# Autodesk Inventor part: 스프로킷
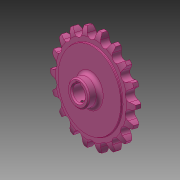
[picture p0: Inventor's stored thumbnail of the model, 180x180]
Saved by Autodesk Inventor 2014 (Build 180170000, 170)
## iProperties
Created: 2016-03
Part Number: 스프로킷
Material: 강철, 탄소
Document SubType Name: Modeling
Designer: mduedu
Density: 7.87 g/cm^3
Mass: 301.818 g
Surface Area: 124.882 cm^2
Volume: 38.3505 cm^3
Appearance: 분홍색
Author: mduedu
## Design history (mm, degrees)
sketch "스케치1"
  geometry: L1 (0, 5)-(29.5, 5); L2 (29.5, 5)-(29.5, 4.1); L3 (30, 3.6)-(33.625, 3.6); L4 (40, 2)-(40, 0); L5 (40, 0)-(0, 0); L6 (0, 0)-(0, 5); L7 (0, -5)-(29.5, -5); L8 (29.5, -5)-(29.5, -4.1); L9 (30, -3.6)-(33.625, -3.6); L10 (40, -2)-(40, 0); L11 (0, 0)-(0, -5); A1 r 13.5 centre (33.625, -9.9) between (40, 2) and (33.625, 3.6); A2 r 13.5 centre (33.625, 9.9) between (33.625, -3.6) and (40, -2); A3 r 0.5 centre (30, 4.1) between (29.5, 4.1) and (30, 3.6); A4 r 0.5 centre (30, -4.1) between (30, -3.6) and (29.5, -4.1); 2 further points
  constraints: 22 end point, 8 point on circle, 6 symmetric about line, 5 tangent, 4 centre point, 4 parallel, 4 point on line, 1 equal radius, 1 horizontal, 1 perpendicular, 1 other
  dimensions: "d0" = 80 diameter of L4 L6; "d2" = 59 diameter of L2 L6; "d3" = 1.6 vertical distance of L4.start L3.end; "d4" = 3.6 distance from line of L4.end L3; "d5" = 5 distance between parallel lines of L5 L1; "d6" = 13.5 radius of A1; "d15" = 0.5 radius of A3
revolve "회전1" sketch "스케치1" stored, may be unused: angle "d7" = 90 deg
sketch "스케치2" dims "d8" = 65.2, "d11" = 80
  geometry: L1 (0, 0)-(0, 32.6); A1 r 36.57 centre (0, 0) between (-16.231, 32.771) and (0, 36.57); A2 r 3.97 centre (0, 36.57) between (-3.866, 35.665) and (0, 32.6); A3 r 12.7 centre (-16.231, 32.771) between (-3.866, 35.665) and (-5.534, 39.615); A4 r 12.7 centre (16.231, 32.771) between (5.534, 39.615) and (3.866, 35.665); A5 r 3.97 centre (0, 36.57) between (0, 32.6) and (3.866, 35.665); A6 r 40 centre (0, 0) between (5.534, 39.615) and (-5.534, 39.615); 2 further points
  constraints: 12 point on circle, 6 centre point, 4 coincident, 3 symmetric about line, 2 end point, 1 point on line, 1 tangent, 1 vertical, 1 vertical alignment, 7 other
  dimensions: "d10" = 73.14 diameter of A1; "d12" = 12.7 radius of A3
extrude "돌출1" cut sketch "스케치2" stored distance "d13" = 10; taper "d14" = 0 deg
sketch "스케치3"
  geometry: C1 r 10 at (0, 0); 1 further point
  constraints: 1 centre point, 1 coincident
  dimensions: "d19" = 20 diameter of C1
extrude "돌출2" join sketch "스케치3" distance "d20" = 9; taper "d21" = 0 deg
fillet "모깎기1" dims "d22" = 3
sketch "스케치4"
  geometry: L1 (-2, 0)-(2, 0); L2 (2, 0)-(2, 7.8); L3 (2, 7.8)-(-2, 7.8); L4 (-2, 7.8)-(-2, 0); C1 r 6 at (0, 0); 2 further points
  constraints: 8 end point, 2 coincident, 2 parallel, 1 centre point, 1 horizontal, 1 midpoint, 1 perpendicular
  dimensions: "d23" = 12 diameter of C1; "d25" = 4 distance of L2.end L3.end; "d26" = 7.8 distance of L1.end L2.end
extrude "돌출3" cut sketch "스케치4" stored distance "d27" = 8; taper "d28" = 0 deg
chamfer "모따기2" distance "d42" = 1; stored, may be unused: second distance "d43" = 2, angle "d44" = 45 deg
node "작업 평면2"
sketch "스케치6"
  geometry: L1 (-9, 14)-(9, 14) reference; 3 further points
  constraints: 2 vertical alignment, 1 midpoint
  dimensions: "d59" = 4 distance from line of point (0, 10) L1
hole "구멍2" sketch "스케치6" at (0, 10) diameter "d48" = 3; stored, may be unused: countersink angle "d52" = 90 deg, drill point angle "d54" = 118 deg; dims "d49" = 6, "d50" = 4, "d51" = 2, "d53" = 8
thread "Thread1" dims "d56" = 10, "d57" = 0
node "솔리드1"
pattern_circular "원형 패턴1" dims angle "d17" = 360 deg
other parameters: "d55" = -13
